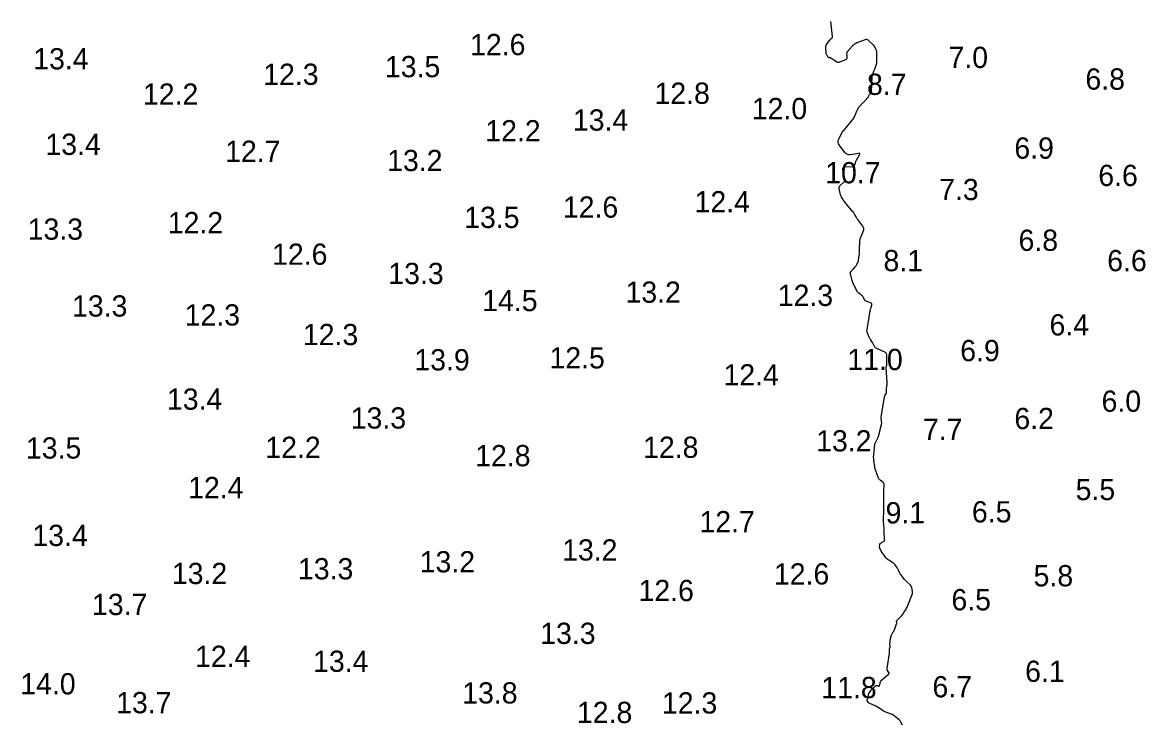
# Model space of a CAD drawing. Extents: x 815352 to 820877, y 582403 to 597439.
# Drawn here: x 820570.7 to 820834.7, y 590177.1 to 590342 of the extents above; entities that cross this region are included whole.
import ezdxf

# ---------------------------------------------------------------- set-up
doc = ezdxf.new("R2010")
doc.units = 0
doc.layers.add('V-CONT-EL12', color=7, linetype='Continuous')
doc.layers.add('V-TOPO-SOUN', color=7, linetype='Continuous')

msp = doc.modelspace()

# ---------------------------------------------------------------- linework, layer by layer
at = {"layer": 'V-CONT-EL12'}
for points in [[(820773.8, 590255.68), (820773.91, 590256.64), (820773.93, 590256.82), (820773.93, 590257), (820773.93, 590257.18), (820773.93, 590257.37), (820773.7, 590260.85), (820773.7, 590260.89), (820773.7, 590260.93), (820773.71, 590260.97), (820773.73, 590261.01), (820773.81, 590261.15), (820773.83, 590261.19), (820773.84, 590261.23), (820773.85, 590261.27), (820773.85, 590261.31), (820773.89, 590263.65), (820773.89, 590263.71), (820773.89, 590263.77), (820773.88, 590263.82), (820773.86, 590263.88), (820773.79, 590264.15), (820773.78, 590264.18), (820773.76, 590264.21), (820773.75, 590264.23), (820773.73, 590264.26), (820773.64, 590264.34), (820773.62, 590264.36), (820773.6, 590264.38), (820773.57, 590264.4), (820773.55, 590264.41), (820771.36, 590265.41), (820771.24, 590265.48), (820771.13, 590265.56), (820771.05, 590265.67), (820770.98, 590265.79), (820770.75, 590266.3), (820770.69, 590266.43), (820770.62, 590266.55), (820770.55, 590266.67), (820770.48, 590266.79), (820770.05, 590267.43), (820769.96, 590267.58), (820769.88, 590267.73), (820769.8, 590267.89), (820769.72, 590268.04), (820769.34, 590268.92), (820769.27, 590269.13), (820769.23, 590269.33), (820769.22, 590269.54), (820769.24, 590269.76), (820769.61, 590271.88), (820769.65, 590272.11), (820769.68, 590272.33), (820769.72, 590272.56), (820769.75, 590272.78), (820769.88, 590273.69), (820769.92, 590273.91), (820769.96, 590274.13), (820770.02, 590274.36), (820770.07, 590274.58), (820770.35, 590275.56), (820770.38, 590275.75), (820770.34, 590275.92), (820770.23, 590276.04), (820770.05, 590276.12), (820769.03, 590276.44), (820768.9, 590276.5), (820768.79, 590276.57), (820768.71, 590276.67), (820768.64, 590276.79), (820768.4, 590277.31), (820768.33, 590277.44), (820768.26, 590277.55), (820768.17, 590277.66), (820768.06, 590277.76), (820767.31, 590278.38), (820767.15, 590278.52), (820767.01, 590278.68), (820766.89, 590278.85), (820766.79, 590279.03), (820766.09, 590280.43), (820765.99, 590280.65), (820765.89, 590280.87), (820765.81, 590281.1), (820765.74, 590281.33), (820765.39, 590282.59), (820765.37, 590282.66), (820765.36, 590282.74), (820765.35, 590282.82), (820765.35, 590282.89), (820765.37, 590283.32), (820765.38, 590283.34), (820765.38, 590283.36), (820765.39, 590283.38), (820765.41, 590283.4), (820765.47, 590283.46), (820765.48, 590283.48), (820765.5, 590283.49), (820765.51, 590283.51), (820765.53, 590283.52), (820765.83, 590283.87), (820765.89, 590283.93), (820765.95, 590283.99), (820766, 590284.06), (820766.06, 590284.12), (820766.51, 590284.62), (820766.6, 590284.73), (820766.69, 590284.84), (820766.76, 590284.96), (820766.83, 590285.09), (820767.18, 590285.8), (820767.19, 590285.83), (820767.2, 590285.86), (820767.21, 590285.89), (820767.22, 590285.92), (820767.24, 590286.04), (820767.24, 590286.07), (820767.24, 590286.1), (820767.25, 590286.13), (820767.25, 590286.16), (820767.39, 590287.29), (820767.42, 590287.48), (820767.43, 590287.68), (820767.45, 590287.88), (820767.45, 590288.08), (820767.47, 590289.09), (820767.48, 590289.3), (820767.49, 590289.51), (820767.5, 590289.72), (820767.51, 590289.93), (820767.57, 590290.77), (820767.59, 590290.98), (820767.63, 590291.18), (820767.69, 590291.38), (820767.77, 590291.57), (820768.4, 590292.99), (820768.49, 590293.28), (820768.5, 590293.57), (820768.43, 590293.84), (820768.27, 590294.11), (820767.03, 590295.71), (820766.92, 590295.85), (820766.82, 590296), (820766.73, 590296.15), (820766.64, 590296.31), (820766.31, 590296.94), (820766.22, 590297.09), (820766.12, 590297.24), (820766.02, 590297.39), (820765.91, 590297.52), (820764.42, 590299.26), (820764.35, 590299.35), (820764.27, 590299.44), (820764.2, 590299.54), (820764.13, 590299.63), (820763.85, 590300), (820763.78, 590300.1), (820763.71, 590300.19), (820763.64, 590300.29), (820763.58, 590300.39), (820763.25, 590300.93), (820763.18, 590301.06), (820763.12, 590301.19), (820763.07, 590301.32), (820763.03, 590301.46), (820762.7, 590303.01), (820762.68, 590303.23), (820762.72, 590303.43), (820762.82, 590303.61), (820762.97, 590303.77), (820763.72, 590304.36), (820763.88, 590304.51), (820763.98, 590304.69), (820764.02, 590304.89), (820764, 590305.12), (820763.53, 590307.27), (820763.51, 590307.59), (820763.6, 590307.82), (820763.8, 590307.98), (820764.11, 590308.04), (820765.99, 590308.19), (820766.13, 590308.22), (820766.24, 590308.28), (820766.32, 590308.38), (820766.38, 590308.51), (820766.53, 590309.11), (820766.57, 590309.26), (820766.62, 590309.4), (820766.69, 590309.54), (820766.76, 590309.68), (820767.46, 590310.86), (820767.55, 590311.06), (820767.53, 590311.2), (820767.41, 590311.26), (820767.19, 590311.24), (820765.33, 590310.92), (820764.95, 590310.9), (820764.61, 590310.98), (820764.3, 590311.15), (820764.03, 590311.43), (820762.66, 590313.22), (820762.49, 590313.5), (820762.41, 590313.79), (820762.42, 590314.09), (820762.52, 590314.4), (820763.36, 590316.21), (820763.38, 590316.26), (820763.41, 590316.3), (820763.44, 590316.34), (820763.48, 590316.37), (820763.64, 590316.51), (820763.68, 590316.54), (820763.71, 590316.58), (820763.75, 590316.62), (820763.78, 590316.66), (820765.8, 590319.11), (820765.96, 590319.31), (820766.1, 590319.53), (820766.22, 590319.75), (820766.33, 590319.99), (820766.85, 590321.22), (820766.89, 590321.32), (820766.94, 590321.42), (820766.99, 590321.52), (820767.03, 590321.62), (820767.24, 590322.01), (820767.29, 590322.11), (820767.35, 590322.2), (820767.42, 590322.28), (820767.5, 590322.36), (820768.2, 590323.03), (820768.34, 590323.17), (820768.48, 590323.31), (820768.62, 590323.46), (820768.75, 590323.6), (820769.48, 590324.43), (820769.52, 590324.47), (820769.55, 590324.52), (820769.58, 590324.57), (820769.6, 590324.62), (820769.72, 590324.92), (820769.73, 590324.92), (820769.73, 590324.93), (820769.73, 590324.94), (820769.73, 590324.95), (820769.73, 590324.98), (820769.73, 590324.99), (820769.74, 590325), (820769.74, 590325.01), (820769.75, 590325.01), (820770.13, 590325.44), (820770.19, 590325.51), (820770.23, 590325.6), (820770.26, 590325.69), (820770.27, 590325.78), (820770.43, 590329.15), (820770.44, 590329.33), (820770.47, 590329.51), (820770.52, 590329.69), (820770.58, 590329.87), (820770.86, 590330.56), (820770.93, 590330.73), (820771, 590330.9), (820771.06, 590331.08), (820771.12, 590331.25), (820771.38, 590331.97), (820771.43, 590332.15), (820771.47, 590332.33), (820771.5, 590332.52), (820771.5, 590332.7), (820771.51, 590335), (820771.5, 590335.17), (820771.47, 590335.33), (820771.42, 590335.49), (820771.35, 590335.64), (820770.91, 590336.5), (820770.89, 590336.53), (820770.88, 590336.55), (820770.86, 590336.57), (820770.85, 590336.59), (820770.78, 590336.66), (820770.76, 590336.68), (820770.75, 590336.7), (820770.73, 590336.71), (820770.72, 590336.73), (820770.65, 590336.79), (820770.64, 590336.81), (820770.62, 590336.83), (820770.61, 590336.84), (820770.59, 590336.86), (820769.57, 590337.8), (820769.39, 590337.93), (820769.2, 590338), (820768.99, 590338.01), (820768.77, 590337.95), (820766.86, 590337.21), (820766.57, 590337.08), (820766.3, 590336.92), (820766.06, 590336.73), (820765.83, 590336.51), (820764.63, 590335.24), (820764.58, 590335.17), (820764.53, 590335.09), (820764.5, 590335.01), (820764.48, 590334.93), (820764.41, 590334.44), (820764.4, 590334.42), (820764.41, 590334.4), (820764.41, 590334.38), (820764.42, 590334.37), (820764.46, 590334.31), (820764.47, 590334.29), (820764.48, 590334.27), (820764.48, 590334.25), (820764.49, 590334.24), (820764.49, 590333.63), (820764.48, 590333.54), (820764.44, 590333.45), (820764.38, 590333.39), (820764.29, 590333.34), (820762.59, 590332.64), (820762.54, 590332.62), (820762.49, 590332.62), (820762.45, 590332.62), (820762.4, 590332.63), (820762.21, 590332.69), (820762.16, 590332.71), (820762.12, 590332.73), (820762.07, 590332.75), (820762.03, 590332.78), (820760.6, 590333.73), (820760.56, 590333.75), (820760.52, 590333.77), (820760.48, 590333.77), (820760.43, 590333.77), (820760.26, 590333.75), (820760.22, 590333.75), (820760.18, 590333.76), (820760.15, 590333.78), (820760.12, 590333.81), (820759.75, 590334.39), (820759.71, 590334.46), (820759.68, 590334.52), (820759.67, 590334.59), (820759.66, 590334.66), (820759.63, 590334.95), (820759.63, 590335.02), (820759.62, 590335.09), (820759.62, 590335.17), (820759.61, 590335.24), (820759.57, 590335.63), (820759.57, 590335.72), (820759.56, 590335.81), (820759.56, 590335.9), (820759.56, 590335.99), (820759.58, 590336.45), (820759.59, 590336.56), (820759.62, 590336.65), (820759.66, 590336.75), (820759.72, 590336.84), (820760.48, 590337.89), (820760.53, 590337.97), (820760.59, 590338.04), (820760.66, 590338.1), (820760.73, 590338.16), (820761, 590338.41), (820761.06, 590338.47), (820761.1, 590338.54), (820761.12, 590338.62), (820761.12, 590338.71), (820760.68, 590342.27)], [(820777.57, 590176.82), (820777.21, 590177.46), (820777.11, 590177.61), (820777, 590177.76), (820776.88, 590177.89), (820776.75, 590178.02), (820775.94, 590178.73), (820775.76, 590178.88), (820775.56, 590179.01), (820775.35, 590179.13), (820775.13, 590179.23), (820773.29, 590179.96), (820773.23, 590179.99), (820773.18, 590180.01), (820773.13, 590180.05), (820773.08, 590180.08), (820772.89, 590180.23), (820772.85, 590180.26), (820772.8, 590180.3), (820772.75, 590180.33), (820772.7, 590180.36), (820771.28, 590181.21), (820771.12, 590181.3), (820770.95, 590181.39), (820770.78, 590181.47), (820770.61, 590181.55), (820769.71, 590181.92), (820769.64, 590181.96), (820769.58, 590182), (820769.52, 590182.06), (820769.47, 590182.12), (820769.3, 590182.39), (820769.27, 590182.46), (820769.25, 590182.53), (820769.26, 590182.6), (820769.27, 590182.68), (820769.46, 590183.18), (820769.5, 590183.27), (820769.52, 590183.36), (820769.54, 590183.45), (820769.55, 590183.55), (820769.6, 590183.93), (820769.61, 590184.02), (820769.64, 590184.11), (820769.67, 590184.2), (820769.72, 590184.28), (820769.95, 590184.67), (820770.01, 590184.76), (820770.07, 590184.85), (820770.14, 590184.93), (820770.21, 590185), (820771.13, 590185.93), (820771.18, 590185.97), (820771.23, 590186), (820771.28, 590186.02), (820771.34, 590186.04), (820771.57, 590186.1), (820771.63, 590186.11), (820771.68, 590186.11), (820771.74, 590186.09), (820771.79, 590186.07), (820771.99, 590185.95), (820772.03, 590185.93), (820772.07, 590185.93), (820772.1, 590185.96), (820772.13, 590186), (820772.24, 590186.31), (820772.26, 590186.38), (820772.28, 590186.45), (820772.3, 590186.52), (820772.32, 590186.59), (820772.41, 590187.01), (820772.44, 590187.1), (820772.48, 590187.19), (820772.53, 590187.26), (820772.6, 590187.33), (820774.29, 590188.74), (820774.37, 590188.83), (820774.41, 590188.92), (820774.4, 590189.03), (820774.35, 590189.13), (820774.05, 590189.58), (820773.99, 590189.69), (820773.95, 590189.81), (820773.94, 590189.94), (820773.95, 590190.07), (820774.51, 590193.67), (820774.53, 590193.76), (820774.53, 590193.85), (820774.53, 590193.94), (820774.53, 590194.02), (820774.5, 590194.37), (820774.5, 590194.46), (820774.5, 590194.55), (820774.51, 590194.63), (820774.52, 590194.72), (820774.63, 590195.16), (820774.63, 590195.2), (820774.64, 590195.25), (820774.64, 590195.29), (820774.63, 590195.33), (820774.61, 590195.5), (820774.61, 590195.54), (820774.6, 590195.58), (820774.61, 590195.63), (820774.61, 590195.67), (820774.77, 590197.13), (820774.8, 590197.34), (820774.85, 590197.54), (820774.92, 590197.73), (820775.01, 590197.92), (820775.4, 590198.67), (820775.5, 590198.86), (820775.59, 590199.05), (820775.67, 590199.24), (820775.74, 590199.44), (820776.18, 590200.62), (820776.2, 590200.69), (820776.21, 590200.75), (820776.21, 590200.82), (820776.21, 590200.89), (820776.18, 590201.16), (820776.18, 590201.23), (820776.19, 590201.29), (820776.22, 590201.35), (820776.26, 590201.4), (820777.32, 590202.46), (820777.48, 590202.64), (820777.64, 590202.82), (820777.78, 590203.02), (820777.91, 590203.22), (820778.4, 590204.06), (820778.52, 590204.27), (820778.63, 590204.48), (820778.74, 590204.7), (820778.83, 590204.92), (820779.85, 590207.49), (820779.91, 590207.68), (820779.94, 590207.88), (820779.94, 590208.08), (820779.91, 590208.29), (820779.73, 590209.1), (820779.67, 590209.3), (820779.58, 590209.48), (820779.47, 590209.65), (820779.33, 590209.8), (820778.43, 590210.64), (820778.28, 590210.79), (820778.12, 590210.95), (820777.98, 590211.12), (820777.84, 590211.29), (820777.22, 590212.1), (820777.13, 590212.22), (820777.05, 590212.36), (820776.97, 590212.49), (820776.9, 590212.63), (820776.64, 590213.2), (820776.57, 590213.35), (820776.49, 590213.48), (820776.41, 590213.62), (820776.32, 590213.75), (820775.82, 590214.47), (820775.7, 590214.63), (820775.56, 590214.77), (820775.41, 590214.9), (820775.24, 590215.01), (820774.23, 590215.61), (820774.02, 590215.76), (820773.82, 590215.92), (820773.64, 590216.11), (820773.49, 590216.32), (820772.63, 590217.61), (820772.58, 590217.69), (820772.53, 590217.77), (820772.48, 590217.86), (820772.44, 590217.95), (820772.26, 590218.3), (820772.22, 590218.39), (820772.2, 590218.48), (820772.18, 590218.58), (820772.18, 590218.67), (820772.21, 590219.19), (820772.23, 590219.3), (820772.27, 590219.39), (820772.33, 590219.47), (820772.42, 590219.53), (820772.89, 590219.8), (820772.94, 590219.84), (820773, 590219.87), (820773.06, 590219.91), (820773.11, 590219.95), (820773.36, 590220.15), (820773.39, 590220.18), (820773.41, 590220.21), (820773.41, 590220.25), (820773.4, 590220.29), (820773.34, 590220.47), (820773.32, 590220.51), (820773.31, 590220.56), (820773.31, 590220.61), (820773.3, 590220.65), (820773.27, 590222.1), (820773.26, 590222.35), (820773.25, 590222.61), (820773.24, 590222.87), (820773.22, 590223.12), (820773.12, 590224.62), (820773.12, 590224.66), (820773.11, 590224.7), (820773.11, 590224.74), (820773.1, 590224.78), (820773.09, 590224.94), (820773.08, 590224.98), (820773.08, 590225.02), (820773.08, 590225.06), (820773.08, 590225.1), (820773.18, 590227.17), (820773.18, 590227.23), (820773.19, 590227.29), (820773.18, 590227.35), (820773.18, 590227.41), (820773.17, 590227.65), (820773.17, 590227.71), (820773.16, 590227.77), (820773.16, 590227.83), (820773.16, 590227.89), (820773.16, 590231.49), (820773.16, 590231.61), (820773.17, 590231.73), (820773.17, 590231.86), (820773.18, 590231.98), (820773.27, 590233.19), (820773.27, 590233.39), (820773.21, 590233.57), (820773.12, 590233.73), (820772.97, 590233.87), (820772.31, 590234.39), (820772.16, 590234.53), (820772.03, 590234.69), (820771.92, 590234.86), (820771.84, 590235.05), (820771.48, 590236.07), (820771.43, 590236.2), (820771.39, 590236.33), (820771.34, 590236.45), (820771.3, 590236.58), (820771.07, 590237.26), (820771.05, 590237.3), (820771.04, 590237.35), (820771.04, 590237.4), (820771.03, 590237.44), (820771.03, 590237.64), (820771.03, 590237.68), (820771.03, 590237.73), (820771.03, 590237.78), (820771.02, 590237.83), (820770.78, 590239.93), (820770.78, 590239.96), (820770.78, 590240), (820770.78, 590240.03), (820770.79, 590240.07), (820770.82, 590240.2), (820770.83, 590240.24), (820770.83, 590240.27), (820770.84, 590240.3), (820770.84, 590240.34), (820770.98, 590241.93), (820770.99, 590242.03), (820771, 590242.13), (820771.01, 590242.22), (820771.01, 590242.32), (820771.05, 590242.7), (820771.07, 590242.79), (820771.09, 590242.88), (820771.12, 590242.97), (820771.16, 590243.06), (820771.63, 590244.02), (820771.69, 590244.13), (820771.73, 590244.24), (820771.78, 590244.35), (820771.82, 590244.46), (820771.98, 590244.91), (820772.02, 590245.03), (820772.05, 590245.14), (820772.09, 590245.26), (820772.12, 590245.37), (820772.65, 590247.46), (820772.65, 590247.47), (820772.66, 590247.48), (820772.66, 590247.5), (820772.66, 590247.51), (820772.66, 590247.56), (820772.67, 590247.57), (820772.67, 590247.58), (820772.67, 590247.6), (820772.67, 590247.61), (820772.57, 590249.07), (820772.57, 590249.12), (820772.57, 590249.17), (820772.57, 590249.22), (820772.57, 590249.27), (820772.6, 590249.57), (820772.6, 590249.58), (820772.6, 590249.58), (820772.6, 590249.59), (820772.6, 590249.6), (820772.6, 590249.63), (820772.6, 590249.64), (820772.6, 590249.65), (820772.6, 590249.66), (820772.6, 590249.67), (820773.34, 590253.96), (820773.37, 590254.07), (820773.4, 590254.18), (820773.45, 590254.28), (820773.5, 590254.38), (820773.78, 590254.86), (820773.81, 590254.92), (820773.83, 590254.98), (820773.84, 590255.05), (820773.84, 590255.12), (820773.8, 590255.4), (820773.8, 590255.47), (820773.8, 590255.54), (820773.8, 590255.61), (820773.8, 590255.68)]]:
    msp.add_lwpolyline(points, dxfattribs=at)

# ---------------------------------------------------------------- texts
at = {"layer": 'V-TOPO-SOUN'}
for s, p in [('12.6 ', (820675.91, 590334.34)), ('13.4 ', (820573.21, 590330.99)), ('7.0', (820788.38, 590331.32)), ('13.5 ', (820655.89, 590329.15)), ('12.3 ', (820627.28, 590327.35)), ('6.8', (820820.57, 590326.23)), ('12.2 ', (820599, 590322.69)), ('12.8 ', (820719.27, 590322.89)), ('8.7', (820769.22, 590324.99)), ('12.0 ', (820742.14, 590319.28)), ('13.4 ', (820700.08, 590316.59)), ('12.2 ', (820679.48, 590314.06)), ('13.4 ', (820576.07, 590310.88)), ('6.9', (820803.87, 590309.99)), ('12.7 ', (820618.32, 590309.24)), ('13.2 ', (820656.41, 590307.07)), ('10.7 ', (820759.4, 590304.19)), ('6.6', (820823.6, 590303.56)), ('7.3', (820786.18, 590300.25)), ('12.4 ', (820728.69, 590297.36)), ('13.5 ', (820674.52, 590293.69)), ('12.6 ', (820697.73, 590296.11)), ('12.2 ', (820604.84, 590292.44)), ('13.3 ', (820571.9, 590290.93)), ('6.8', (820804.85, 590288.31)), ('12.6 ', (820629.36, 590285.03)), ('8.1', (820773.1, 590283.52)), ('6.6', (820825.7, 590283.52)), ('13.3 ', (820656.68, 590280.5)), ('13.2 ', (820712.45, 590276.1)), ('12.3 ', (820748.24, 590275.35)), ('13.3 ', (820582.33, 590272.85)), ('14.5 ', (820678.76, 590274.13)), ('12.3 ', (820608.81, 590270.75)), ('6.4', (820812.13, 590268.42)), ('12.3 ', (820636.6, 590266.13)), ('6.9', (820791.14, 590262.36)), ('13.9 ', (820662.81, 590260.19)), ('12.5 ', (820694.57, 590260.65)), ('11.0 ', (820764.61, 590260.26)), ('12.4 ', (820735.48, 590256.65)), ('13.4 ', (820604.64, 590250.94)), ('6.0', (820824.37, 590250.45)), ('13.3 ', (820647.85, 590246.51)), ('6.2', (820803.87, 590246.38)), ('7.7', (820782.38, 590243.85)), ('13.2 ', (820757.27, 590241.13)), ('13.5 ', (820571.5, 590239.45)), ('12.2 ', (820627.77, 590239.59)), ('12.8 ', (820716.58, 590239.62)), ('12.8 ', (820677.11, 590237.65)), ('12.4 ', (820609.63, 590230.14)), ('5.5', (820818.27, 590229.68)), ('9.1', (820773.59, 590224.2)), ('6.5', (820793.89, 590224.43)), ('12.7 ', (820729.84, 590222.1)), ('13.4 ', (820573.01, 590218.88)), ('13.2 ', (820697.55, 590215.47)), ('13.2 ', (820664.06, 590212.68)), ('13.2 ', (820605.79, 590209.93)), ('13.3 ', (820635.45, 590211.04)), ('12.6 ', (820747.34, 590209.83)), ('5.8', (820808.39, 590209.4)), ('12.6 ', (820715.51, 590205.92)), ('13.7 ', (820587.02, 590202.64)), ('6.5', (820789.07, 590203.76)), ('13.3 ', (820692.4, 590195.85)), ('12.4 ', (820611.24, 590190.44)), ('13.4 ', (820638.99, 590189.29)), ('6.1', (820806.4, 590186.93)), ('14.0 ', (820570.16, 590183.98)), ('11.8 ', (820758.48, 590183.09)), ('6.7', (820784.61, 590183.29)), ('13.8 ', (820674.06, 590181.84)), ('13.7 ', (820592.7, 590179.55)), ('12.3 ', (820721.01, 590179.48)), ('12.8 ', (820701.03, 590177.25))]:
    msp.add_text(s, height=5, dxfattribs=at).set_placement(p)

doc.saveas('drawing.dxf')
